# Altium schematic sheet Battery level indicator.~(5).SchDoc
size A3; SheetNumber: 3; SheetTotal: 3
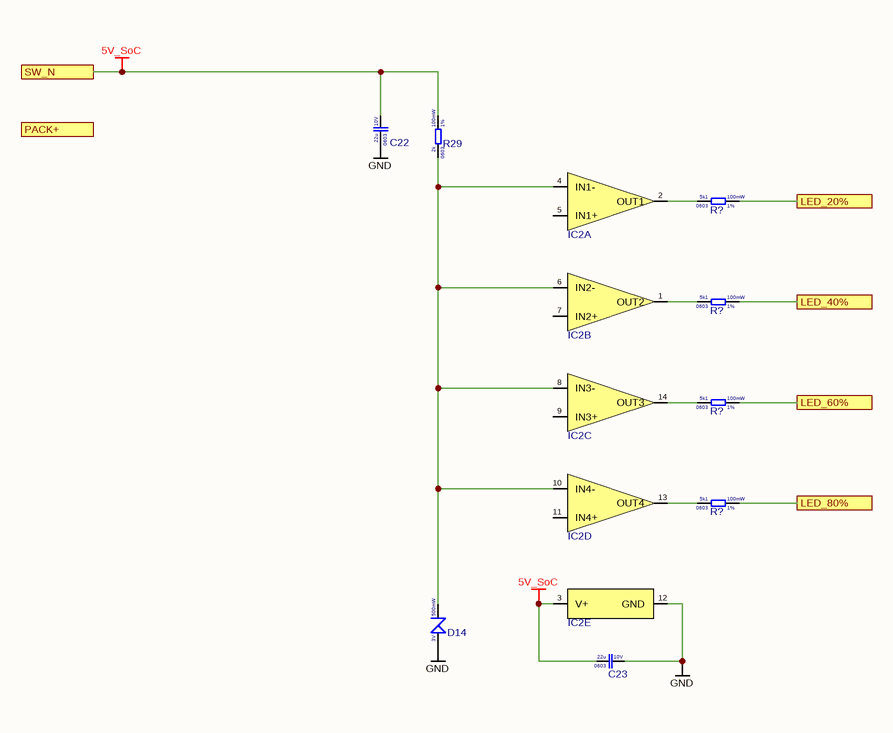
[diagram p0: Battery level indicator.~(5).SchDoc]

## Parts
(Parts that share a designator on the sheet are numbered #1, #2 ... from top to bottom, then left to right.)
C22  Voltage Rating: 10V  Case Code (Imperial): 0603  Capacitance: 22u  [CAP 0603]  (hidden comment: CGA0603X5R226M100JT)
C23  Voltage Rating: 10V  Case Code (Imperial): 0603  Capacitance: 22u  [CAP 0603]  (hidden comment: CGA0603X5R226M100JT)
D14  Power Rating: 500mW  Reverse Voltage: 3V  [SOD-123]  (hidden comment: BZT52C3V0)
IC2  LM339LVPWR  [TSSOP-14]  (value not drawn)  (parts A,B,C,D,E of 5)
R29  Resistance Tolerance: 1%  Resistance: 2k  Power Rating: 100mW  Case Code (Imperial): 0603  [RES_0603]  (hidden comment: 0603WAF2001T5E)
R?#1  Resistance Tolerance: 1%  Resistance: 5k1  Power Rating: 100mW  Case Code (Imperial): 0603  [RES_0603]  (hidden comment: 0603WAF5101T5E)
R?#2  Resistance Tolerance: 1%  Resistance: 5k1  Power Rating: 100mW  Case Code (Imperial): 0603  [RES_0603]  (hidden comment: 0603WAF5101T5E)
R?#3  Resistance Tolerance: 1%  Resistance: 5k1  Power Rating: 100mW  Case Code (Imperial): 0603  [RES_0603]  (hidden comment: 0603WAF5101T5E)
R?#4  Resistance Tolerance: 1%  Resistance: 5k1  Power Rating: 100mW  Case Code (Imperial): 0603  [RES_0603]  (hidden comment: 0603WAF5101T5E)

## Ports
LED_20% (see Arhitecture[8C]), LED_40% (see Arhitecture[8C]), LED_60% (see Arhitecture[8C]), LED_80% (see Arhitecture[8D]), PACK+ (see Arhitecture[7C], Charger[8A]), SW_N (see Arhitecture[7D])

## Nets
5V_SoC: C22.2 C23.1 IC2.3(V+) R29.2 ; port SW_N
GND: C22.1 C23.2 D14.A IC2.12(GND)
LED_20%: R?#1.2 ; port LED_20%
LED_40%: R?#2.2 ; port LED_40%
LED_60%: R?#3.2 ; port LED_60%
LED_80%: R?#4.2 ; port LED_80%
NetD14_K: D14.K IC2.4(IN1-) IC2.6(IN2-) IC2.8(IN3-) IC2.10(IN4-) R29.1
NetIC2_1: IC2.1(OUT2) R?#2.1
NetIC2_2: IC2.2(OUT1) R?#1.1
NetIC2_13: IC2.13(OUT4) R?#4.1
NetIC2_14: IC2.14(OUT3) R?#3.1

Not connected (* = marked no-connect by the designer): IC2 5(IN1+) 7(IN2+) 9(IN3+) 11(IN4+)

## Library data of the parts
C22 C23 = CGA0603X5R226M100JT: Cap 22uF 10V 0603 X5R; Manufacturer: HRE
D14 = BZT52C3V0: Zener 3.0V 500mW SOD-123; Manufacturer: Shandong Jingdao Microelectronics
IC2 = LM339LVPWR: Comparator Quad 1.65~5.5V TSSOP-14; Manufacturer: Texas Instruments
R29 = 0603WAF2001T5E: Res 2k 0603 1% 100mW 75V; Manufacturer: Uni-Royal
R?#1-R?#4 = 0603WAF5101T5E: Res 5k1 0603 1% 100mW 75V; Manufacturer: Uni-Royal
